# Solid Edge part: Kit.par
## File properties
Dokumentum tartalom típus: 0
Last saved by: psaghy
Revision: 77
Sűrűség: 0,000 kg/m^3
Pontosság: 0,990
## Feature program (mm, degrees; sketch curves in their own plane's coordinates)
base feature "unnamed BaseFeature 1"
sketch for "Furat_1" plane through (0, 0, 39) normal (0, 0, 1) x-axis (0, -1, 0)
  hole centre (-23.25, 23.25) bore radius 3.3235
hole "Furat_1" nominal diameter 8 finite  VBottomAngle = 118 deg; ThreadDepth = 16 mm
sketch for "unnamed Hole 1" plane through (0, 0, 39) normal (0, 0, 1) x-axis (0, -1, 0)
  hole centre (-23.25, -23.25) bore radius 3.3235
hole "unnamed Hole 1" finite
sketch for "unnamed Hole 2" plane through (0, 0, 39) normal (0, 0, 1) x-axis (0, -1, 0)
  hole centre (23.25, -23.25) bore radius 3.3235
hole "unnamed Hole 2" finite
sketch for "unnamed Hole 3" plane through (0, 0, 39) normal (0, 0, 1) x-axis (0, -1, 0)
  hole centre (23.25, 23.25) bore radius 3.3235
hole "unnamed Hole 3" finite
pattern "unnamed Pattern 1" of "Furat_1", "unnamed Hole 1", "unnamed Hole 2", "unnamed Hole 3"
sketch for "Furat_5" plane through (32.5, 0.0003, 21.2488) normal (1, 0, 0) x-axis (0, 0, -1)
hole "Furat_5" diameter 13.157 finite  ThreadDepth = 10 mm
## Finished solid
Body 1: solid body, 446 faces, 1036 edges, 651 vertices, 7 internal voids.
  Faces by surface: plane 155, cylinder 135, torus 52, cone 51, sphere 23, spline 21, swept 9
  Edges by curve: line 368, circle 356, curve on surface 286, spline 26
Bounding box of the edges (mm; curved faces can reach further): 65.000 x 65.000 x 56.500, from (-32.5, -32.5, 8) to (32.5002, 32.5, 64.5).
Cylindrical faces by radius (mm): R0.3125 x1, R0.3838 x1, R0.4089 x1, R0.4253 x1, R0.4408 x1, R0.5 x8, R0.5003 x1, R0.5483 x1, R0.5961 x1, R0.615 x1, R0.6311 x1, R0.6362 x1, R0.652 x1, R0.6792 x1, R0.73 x1, R0.7378 x1, R0.7396 x1, R0.9114 x1, R1 x20, R1.0004 x7, R1.001 x6, R1.0014 x8, R1.0015 x1, R1.0026 x1, R1.0394 x1, R1.0539 x1, R1.0734 x1, R1.0987 x1, R1.1871 x1, R1.2561 x1, R1.2722 x2, R1.3621 x1, R1.3711 x1, R1.4 x1, R1.7143 x1, R3.3235 x8, R4 x4, R4.15 x4, R4.5 x1, R5 x2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
Conical faces (half-angle, radius in mm at the cone's reference point): 0.5 deg R18.5 x4, 0.5 deg R22.25 x4, 1.6538 deg R11.75 x1, 3.5477 deg R12.7454 x1, 5.762 deg R10.4 x1, 11.1239 deg R10.0056 x1, 15 deg R18.5156 x1, 15.3654 deg R10.7214 x1, 19.3654 deg R11.1921 x1, 25.0169 deg R14.31 x1, 30 deg R5.1443 x1, 30 deg R11.8557 x2, 30 deg R12.1443 x1, 30 deg R19.5 x1, 31.4296 deg R28.625 x4, 45 deg R2.75 x1, 45 deg R2.825 x1, 45 deg R4.3 x8, 45 deg R6.35 x8, 45 deg R6.72 x1, 45 deg R10.15 x2, 45 deg R15.25 x1, 59 deg R3.3235 x4
Toroidal faces (ring radius, tube radius in mm): R0.4909 r0.5044 x1, R0.5094 r0.5004 x1, R0.8674 r0.5067 x1, R1.4976 r0.5003 x6, R4.3 r0.3 x4, R4.7 r0.3 x1, R6.45 r0.2 x4, R7.15 r0.5 x4, R9.5 r0.5 x1, R9.75 r0.5 x2, R10.3 r0.3 x1, R10.3085 r0.3 x1, R11.4279 r0.25 x1, R12.2464 r0.5 x1, R13.9897 r0.5062 x1, R14.8 r0.2 x1, R17 r2 x1, R17.6163 r0.5 x1, R19.4739 r1 x1, R19.4913 r1 x3, R20.5 r0.5 x1, R21.2587 r1 x3, R21.2761 r1 x1, R27.25 r1 x3, R31.75 r1 x6, R33.3108 r1 x1
Spherical faces by radius (mm): R0.5 x1, R1 x22
Planar faces by outward normal: +x 24, +y 9, +z 36, -x 5, -y 8, -z 24, oblique 49
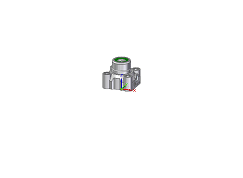
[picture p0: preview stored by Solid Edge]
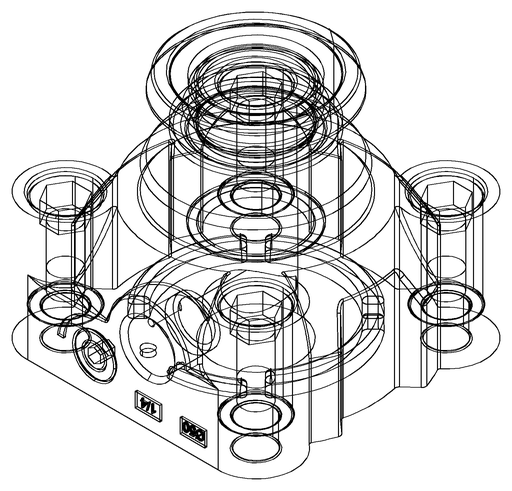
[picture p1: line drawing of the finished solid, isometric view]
